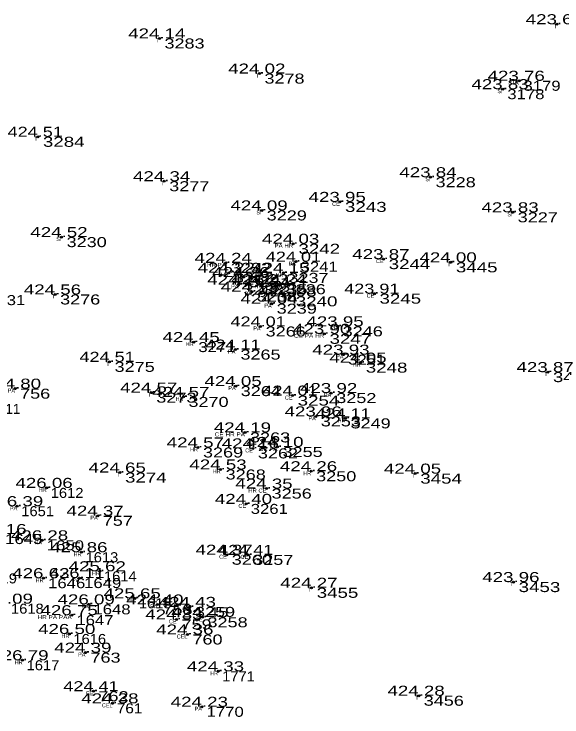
# Model space of a CAD drawing. Extents: x -639390 to -639074, y -1138747 to -1138358.
# Drawn here: x -639242.7 to -639201.6, y -1138570 to -1138517.3 of the extents above; entities that cross this region are included whole.
import ezdxf
from ezdxf.enums import TextEntityAlignment as Align

# ---------------------------------------------------------------- set-up
doc = ezdxf.new("R2010")
doc.units = 0
doc.header["$LTSCALE"] = 0.3
doc.header["$PDMODE"] = 32
doc.header["$PDSIZE"] = 0.15
for name, color, linetype in [('11', 7, 'Continuous'), ('12', 7, 'Continuous'), ('13', 7, 'Continuous'), ('57', 7, 'Continuous')]:
    doc.layers.add(name, color=color, linetype=linetype)

msp = doc.modelspace()

# ---------------------------------------------------------------- linework, layer by layer
at = {"layer": '11'}
for p in [(-639201.95, -1138518.05), (-639231.77, -1138519.12), (-639224.27, -1138521.75), (-639204.81, -1138522.29), (-639206.02, -1138522.92), (-639240.9, -1138526.49), (-639211.43, -1138529.52), (-639231.41, -1138529.82), (-639218.24, -1138531.37), (-639224.1, -1138532.01), (-639205.27, -1138532.15), (-639239.11, -1138534.01), (-639221.73, -1138534.51), (-639226.79, -1138535.94), (-639221.53, -1138535.85), (-639214.96, -1138535.66), (-639209.92, -1138535.9), (-639226.56, -1138536.68), (-639225.46, -1138537.01), (-639222.47, -1138536.69), (-639225.84, -1138537.57), (-639224.05, -1138537.54), (-639222.68, -1138537.54), (-639224.83, -1138538.1), (-639239.6, -1138538.31), (-639221.93, -1138538.45), (-639215.65, -1138538.25), (-639223.35, -1138539), (-639224.18, -1138540.71), (-639218.4, -1138540.7), (-639219.4, -1138541.26), (-639229.2, -1138541.88), (-639226.07, -1138542.44), (-639217.96, -1138542.82), (-639235.51, -1138543.36), (-639216.68, -1138543.42), (-639202.64, -1138544.13), (-639242.6, -1138545.37), (-639226.05, -1138545.18), (-639232.38, -1138545.67), (-639229.97, -1138545.99), (-639221.79, -1138545.89), (-639218.88, -1138545.7), (-639220.04, -1138547.45), (-639217.81, -1138547.6), (-639225.35, -1138548.65), (-639228.88, -1138549.78), (-639224.76, -1138549.85), (-639222.91, -1138549.74), (-639234.74, -1138551.66), (-639227.18, -1138551.43), (-639220.39, -1138551.56), (-639212.59, -1138551.74), (-639240.23, -1138552.81), (-639223.73, -1138552.86), (-639242.44, -1138554.18), (-639225.27, -1138554.01), (-639236.4, -1138554.9), (-639240.57, -1138556.74), (-639237.62, -1138557.63), (-639226.72, -1138557.82), (-639225.11, -1138557.83), (-639236.24, -1138559.06), (-639240.47, -1138559.58), (-639237.77, -1138559.57), (-639205.21, -1138559.87), (-639220.36, -1138560.3), (-639233.62, -1138561.09), (-639237.07, -1138561.54), (-639231.92, -1138561.55), (-639229.48, -1138561.73), (-639238.35, -1138562.35), (-639230.49, -1138562.67), (-639228.54, -1138562.51), (-639238.53, -1138563.76), (-639229.67, -1138563.8), (-639237.32, -1138565.16), (-639242.04, -1138565.73), (-639227.37, -1138566.56), (-639236.72, -1138568.05), (-639212.32, -1138568.39), (-639235.29, -1138568.96), (-639228.58, -1138569.22)]:
    msp.add_point(p, dxfattribs=at)

# ---------------------------------------------------------------- texts
at = {"layer": '12'}
for s, width, p in [('423.69 ', 1.4, (-639201.95, -1138518.05)), ('424.14 ', 1.4, (-639231.77, -1138519.12)), ('424.02 ', 1.4, (-639224.27, -1138521.75)), ('423.76 ', 1.4, (-639204.809, -1138522.29)), ('423.83 ', 1.4, (-639206.02, -1138522.92)), ('424.51 ', 1.35, (-639240.899, -1138526.49)), ('424.34 ', 1.4, (-639231.41, -1138529.82)), ('423.84 ', 1.4, (-639211.43, -1138529.52)), ('423.95 ', 1.4, (-639218.24, -1138531.37)), ('424.09 ', 1.4, (-639224.1, -1138532.01)), ('423.83 ', 1.4, (-639205.27, -1138532.15)), ('424.52 ', 1.4, (-639239.11, -1138534.01)), ('424.03 ', 1.4, (-639221.73, -1138534.51)), ('424.24 ', 1.4, (-639226.79, -1138535.94)), ('424.01 ', 1.35, (-639221.529, -1138535.85)), ('423.87 ', 1.4, (-639214.96, -1138535.66)), ('424.00 ', 1.4, (-639209.92, -1138535.9)), ('424.22 ', 1.4, (-639226.56, -1138536.68)), ('424.15 ', 1.4, (-639222.47, -1138536.69)), ('424.26 ', 1.4, (-639225.459, -1138537.01)), ('424.16 ', 1.4, (-639225.839, -1138537.57)), ('424.23 ', 1.4, (-639224.05, -1138537.54)), ('424.24 ', 1.4, (-639222.68, -1138537.54)), ('424.13 ', 1.4, (-639224.83, -1138538.1)), ('423.91 ', 1.35, (-639215.649, -1138538.25)), ('424.56 ', 1.4, (-639239.599, -1138538.31)), ('423.98 ', 1.4, (-639221.93, -1138538.45)), ('424.04 ', 1.4, (-639223.35, -1138539)), ('424.01 ', 1.35, (-639224.179, -1138540.71)), ('423.95 ', 1.4, (-639218.4, -1138540.7)), ('423.90 ', 1.4, (-639219.4, -1138541.26)), ('424.45 ', 1.4, (-639229.2, -1138541.88)), ('424.11 ', 1.35, (-639226.069, -1138542.44)), ('423.93 ', 1.4, (-639217.96, -1138542.82)), ('424.51 ', 1.35, (-639235.509, -1138543.36)), ('424.05 ', 1.4, (-639216.68, -1138543.42)), ('423.87 ', 1.4, (-639202.64, -1138544.13)), ('424.80 ', 1.4, (-639242.6, -1138545.37)), ('424.57 ', 1.4, (-639232.38, -1138545.67)), ('424.05 ', 1.4, (-639226.05, -1138545.18)), ('424.57 ', 1.4, (-639229.97, -1138545.99)), ('424.01 ', 1.35, (-639221.789, -1138545.89)), ('423.92 ', 1.4, (-639218.88, -1138545.7)), ('423.96 ', 1.4, (-639220.039, -1138547.45)), ('424.11 ', 1.35, (-639217.809, -1138547.6)), ('424.19 ', 1.4, (-639225.35, -1138548.65)), ('424.57 ', 1.4, (-639228.88, -1138549.78)), ('424.16 ', 1.4, (-639224.759, -1138549.85)), ('424.10 ', 1.4, (-639222.91, -1138549.74)), ('424.53 ', 1.4, (-639227.18, -1138551.43)), ('424.65 ', 1.4, (-639234.74, -1138551.66)), ('424.26 ', 1.4, (-639220.389, -1138551.56)), ('424.05 ', 1.4, (-639212.59, -1138551.74)), ('426.06 ', 1.4, (-639240.229, -1138552.81)), ('424.35 ', 1.4, (-639223.73, -1138552.86)), ('424.40 ', 1.4, (-639225.27, -1138554.01)), ('426.39 ', 1.4, (-639242.44, -1138554.18)), ('424.37 ', 1.4, (-639236.4, -1138554.9)), ('427.16 ', 1.4, (-639243.689, -1138556.27)), ('426.28 ', 1.4, (-639240.57, -1138556.74)), ('425.86 ', 1.4, (-639237.619, -1138557.63)), ('424.37 ', 1.4, (-639226.72, -1138557.82)), ('424.41 ', 1.35, (-639225.109, -1138557.83)), ('425.62 ', 1.4, (-639236.24, -1138559.06)), ('426.63 ', 1.4, (-639240.47, -1138559.58)), ('426.11 ', 1.35, (-639237.769, -1138559.57)), ('423.96 ', 1.4, (-639205.209, -1138559.87)), ('424.27 ', 1.4, (-639220.36, -1138560.3)), ('425.65 ', 1.4, (-639233.62, -1138561.09)), ('427.09 ', 1.4, (-639243.21, -1138561.49)), ('426.09 ', 1.4, (-639237.07, -1138561.54)), ('424.40 ', 1.4, (-639231.92, -1138561.55)), ('424.43 ', 1.4, (-639229.48, -1138561.73)), ('426.75 ', 1.4, (-639238.35, -1138562.35)), ('424.45 ', 1.4, (-639228.54, -1138562.51)), ('424.33 ', 1.4, (-639230.49, -1138562.67)), ('426.50 ', 1.4, (-639238.53, -1138563.76)), ('424.36 ', 1.4, (-639229.669, -1138563.8)), ('424.39 ', 1.4, (-639237.32, -1138565.16)), ('426.79 ', 1.4, (-639242.04, -1138565.73)), ('424.33 ', 1.4, (-639227.37, -1138566.56)), ('424.41 ', 1.35, (-639236.719, -1138568.05)), ('424.28 ', 1.4, (-639212.32, -1138568.39)), ('424.38 ', 1.4, (-639235.29, -1138568.96)), ('424.23 ', 1.4, (-639228.58, -1138569.22))]:
    msp.add_text(s, height=0.75, dxfattribs=dict(at, width=width)).set_placement(p, align=Align.CENTER)
at = {"layer": '13'}
for s, width, p in [(' 3283', 1.35, (-639231.77, -1138519.87)), (' 3278', 1.35, (-639224.27, -1138522.5)), (' 3179', 1.25, (-639204.81, -1138523.04)), (' 3178', 1.25, (-639206.02, -1138523.67)), (' 3284', 1.4, (-639240.9, -1138527.24)), (' 3228', 1.35, (-639211.43, -1138530.27)), (' 3277', 1.35, (-639231.41, -1138530.57)), (' 3243', 1.4, (-639218.24, -1138532.12)), (' 3229', 1.35, (-639224.1, -1138532.76)), (' 3227', 1.35, (-639205.27, -1138532.9)), (' 3230', 1.35, (-639239.11, -1138534.76)), (' 3242', 1.4, (-639221.73, -1138535.26)), (' 3232', 1.35, (-639226.79, -1138536.69)), (' 3241', 1.25, (-639221.53, -1138536.6)), (' 3244', 1.4, (-639214.96, -1138536.41)), (' 3445', 1.4, (-639209.92, -1138536.65)), (' 3272', 1.35, (-639226.56, -1138537.43)), (' 3234', 1.4, (-639225.46, -1138537.76)), (' 3237', 1.35, (-639222.47, -1138537.44)), (' 3235', 1.35, (-639224.05, -1138538.29)), (' 3236', 1.35, (-639222.68, -1138538.29)), (' 3233', 1.35, (-639225.84, -1138538.32)), (' 3231', 1.25, (-639244.97, -1138539.11)), (' 3276', 1.35, (-639239.6, -1138539.06)), (' 3238', 1.35, (-639224.83, -1138538.85)), (' 3240', 1.4, (-639221.93, -1138539.2)), (' 3245', 1.4, (-639215.65, -1138539)), (' 3239', 1.35, (-639223.35, -1138539.75)), (' 3246', 1.35, (-639218.4, -1138541.45)), (' 3266', 1.35, (-639224.18, -1138541.46)), (' 3247', 1.4, (-639219.4, -1138542.01)), (' 3271', 1.25, (-639229.2, -1138542.63)), (' 3265', 1.35, (-639226.07, -1138543.19)), (' 3251', 1.25, (-639217.96, -1138543.57)), (' 3275', 1.35, (-639235.51, -1138544.11)), (' 3248', 1.4, (-639216.68, -1138544.17)), (' 3446', 1.4, (-639202.64, -1138544.88)), (' 756', 1.35, (-639242.6, -1138546.12)), (' 3264', 1.35, (-639226.05, -1138545.93)), (' 3273', 1.35, (-639232.38, -1138546.42)), (' 3254', 1.4, (-639221.79, -1138546.64)), (' 3252', 1.35, (-639218.88, -1138546.45)), (' 3270', 1.35, (-639229.97, -1138546.74)), (' 3253', 1.35, (-639220.04, -1138548.2)), (' 3249', 1.35, (-639217.81, -1138548.35)), (' 3263', 1.35, (-639225.35, -1138549.4)), (' 3269', 1.35, (-639228.88, -1138550.53)), (' 3262', 1.35, (-639224.76, -1138550.6)), (' 3255', 1.35, (-639222.91, -1138550.49)), (' 3274', 1.4, (-639234.74, -1138552.41)), (' 3268', 1.35, (-639227.18, -1138552.18)), (' 3250', 1.35, (-639220.39, -1138552.31)), (' 3454', 1.4, (-639212.59, -1138552.49)), (' 1612', 1.1, (-639240.23, -1138553.56)), (' 3256', 1.35, (-639223.73, -1138553.61)), (' 1651', 1.1, (-639242.44, -1138554.93)), (' 3261', 1.25, (-639225.27, -1138554.76)), (' 757', 1.35, (-639236.4, -1138555.65)), (' 1645', 1.25, (-639243.69, -1138557.02)), (' 1650', 1.25, (-639240.57, -1138557.49)), (' 1613', 1.1, (-639237.62, -1138558.38)), (' 3260', 1.35, (-639226.72, -1138558.57)), (' 3257', 1.35, (-639225.11, -1138558.58)), (' 1614', 1.1, (-639236.24, -1138559.81)), (' 1619', 1.1, (-639245.22, -1138559.97)), (' 1646', 1.25, (-639240.47, -1138560.33)), (' 1649', 1.25, (-639237.77, -1138560.32)), (' 3453', 1.4, (-639205.21, -1138560.62)), (' 3455', 1.4, (-639220.36, -1138561.05)), (' 1615', 1.1, (-639233.62, -1138561.84)), (' 1618', 1.1, (-639243.21, -1138562.24)), (' 1648', 1.25, (-639237.07, -1138562.29)), (' 758', 1.35, (-639231.92, -1138562.3)), (' 3259', 1.35, (-639229.48, -1138562.48)), (' 1647', 1.25, (-639238.35, -1138563.1)), (' 759', 1.35, (-639230.49, -1138563.42)), (' 3258', 1.35, (-639228.54, -1138563.26)), (' 1616', 1.1, (-639238.53, -1138564.51)), (' 760', 1.35, (-639229.67, -1138564.55)), (' 763', 1.35, (-639237.32, -1138565.91)), (' 1617', 1.1, (-639242.04, -1138566.48)), (' 1771', 1.1, (-639227.37, -1138567.31)), (' 762', 1.35, (-639236.72, -1138568.8)), (' 3456', 1.35, (-639212.32, -1138569.14)), (' 761', 1.15, (-639235.29, -1138569.71)), (' 1770', 1.25, (-639228.58, -1138569.97))]:
    msp.add_text(s, height=0.75, dxfattribs=dict(at, width=width)).set_placement(p)
msp.add_text(' 1611', height=0.75, dxfattribs=at).set_placement((-639244.72, -1138547.26))
at = {"layer": '57'}
for s, width, p in [('T', 0.85, (-639201.95, -1138518.35)), ('T', 0.85, (-639231.77, -1138519.42)), ('T', 0.85, (-639224.27, -1138522.05)), ('SIA', 1.25, (-639204.81, -1138522.59)), ('SI', 1.05, (-639206.02, -1138523.22)), ('T', 0.85, (-639240.9, -1138526.79)), ('SI', 1.05, (-639211.43, -1138529.82)), ('T', 0.85, (-639231.41, -1138530.12)), ('CE', 0.9, (-639218.24, -1138531.67)), ('SI', 1.05, (-639224.1, -1138532.31)), ('SI', 1.05, (-639205.27, -1138532.45)), ('SI', 1.05, (-639239.11, -1138534.31)), ('PA HR', 1.15, (-639221.729, -1138534.81)), ('HR PA', 1.15, (-639226.79, -1138536.24)), ('PA', 0.95, (-639221.53, -1138536.15)), ('CE', 0.9, (-639214.96, -1138535.96)), ('T', 0.85, (-639209.92, -1138536.2)), ('HR', 0.85, (-639226.559, -1138536.98)), ('HR', 0.85, (-639222.469, -1138536.99)), ('HR', 0.85, (-639225.459, -1138537.31)), ('PA', 0.95, (-639225.84, -1138537.87)), ('HR', 0.85, (-639224.049, -1138537.84)), ('HR', 0.85, (-639222.679, -1138537.84)), ('T', 0.85, (-639239.6, -1138538.61)), ('PA', 0.95, (-639224.83, -1138538.4)), ('PA', 0.95, (-639221.93, -1138538.75)), ('CE', 0.9, (-639215.65, -1138538.55)), ('PA', 0.95, (-639223.35, -1138539.3)), ('PA', 0.95, (-639224.18, -1138541.01)), ('CE', 0.9, (-639218.4, -1138541)), ('CE PA HR', 1.2, (-639219.399, -1138541.56)), ('HR', 0.85, (-639229.199, -1138542.18)), ('PA', 0.95, (-639226.07, -1138542.74)), ('PA', 0.95, (-639217.96, -1138543.12)), ('T', 0.85, (-639235.51, -1138543.66)), ('HR', 0.85, (-639216.679, -1138543.72)), ('T', 0.85, (-639202.64, -1138544.43)), ('PA', 0.95, (-639242.6, -1138545.67)), ('PA', 0.95, (-639226.05, -1138545.48)), ('T', 0.85, (-639232.38, -1138545.97)), ('CE', 0.9, (-639221.79, -1138546.19)), ('PA', 0.95, (-639218.88, -1138546)), ('HR', 0.85, (-639229.969, -1138546.29)), ('PA', 0.95, (-639220.04, -1138547.75)), ('HR', 0.85, (-639217.809, -1138547.9)), ('CE HR PA', 1.2, (-639225.35, -1138548.95)), ('HR', 0.85, (-639228.879, -1138550.08)), ('CE', 0.9, (-639224.76, -1138550.15)), ('CE PA', 1.15, (-639222.91, -1138550.04)), ('T', 0.85, (-639234.74, -1138551.96)), ('HR', 0.85, (-639227.179, -1138551.73)), ('HR', 0.85, (-639220.389, -1138551.86)), ('T', 0.85, (-639212.59, -1138552.04)), ('HR', 0.85, (-639240.229, -1138553.11)), ('HR CE', 1.1, (-639223.73, -1138553.16)), ('PA', 0.95, (-639242.44, -1138554.48)), ('CE', 0.9, (-639225.27, -1138554.31)), ('PA', 0.95, (-639236.4, -1138555.2)), ('PA', 0.95, (-639240.57, -1138557.04)), ('HR', 0.85, (-639237.619, -1138557.93)), ('CE', 0.9, (-639226.72, -1138558.12)), ('CE', 0.9, (-639225.11, -1138558.13)), ('HR', 0.85, (-639236.239, -1138559.36)), ('HR', 0.85, (-639240.469, -1138559.88)), ('PA', 0.95, (-639237.77, -1138559.87)), ('T', 0.85, (-639205.21, -1138560.17)), ('T', 0.85, (-639220.36, -1138560.6)), ('HR', 0.85, (-639233.619, -1138561.39)), ('PA', 0.95, (-639237.07, -1138561.84)), ('PA', 0.95, (-639231.92, -1138561.85)), ('CE', 0.9, (-639229.48, -1138562.03)), ('HR PA PAA', 1.2, (-639238.35, -1138562.65)), ('CE', 0.9, (-639230.49, -1138562.97)), ('CE', 0.9, (-639228.54, -1138562.81)), ('HR', 0.85, (-639238.529, -1138564.06)), ('PA', 0.95, (-639237.32, -1138565.46)), ('HR', 0.85, (-639242.039, -1138566.03)), ('HR', 0.85, (-639227.369, -1138566.86)), ('CE', 0.9, (-639236.72, -1138568.35)), ('T', 0.85, (-639212.32, -1138568.69)), ('PA', 0.95, (-639228.58, -1138569.52))]:
    msp.add_text(s, height=0.3, dxfattribs=dict(at, width=width)).set_placement(p, align=Align.RIGHT)
for p in [(-639229.669, -1138564.1), (-639235.289, -1138569.26)]:
    msp.add_text('CEL', height=0.3, dxfattribs=at).set_placement(p, align=Align.RIGHT)

doc.saveas('drawing.dxf')
